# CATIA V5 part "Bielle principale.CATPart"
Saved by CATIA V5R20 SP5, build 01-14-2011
Part number: Bielle principale
Bounding box of the stored display mesh (mm): x -260 to -155, y -330 to 110, z -45 to 85
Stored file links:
  U:\CFAO\Thinkmotion\Bielle principale.CATPart
  U:\CFAO\Thinkmotion\Bras Articule.CATProduct
  U:\CFAO\Thinkmotion\Squelette Bielle principale.CATPart
  U:\CFAO\Thinkmotion\Squelette Corps verin 2.CATPart
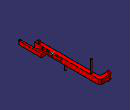
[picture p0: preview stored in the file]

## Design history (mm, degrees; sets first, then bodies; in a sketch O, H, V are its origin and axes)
Set1
  Plane1: linked copy from another document
  Line1: linked copy from another document
  Line2: linked copy from another document
  Point1: linked copy from another document
  Point2: linked copy from another document
  Line3: linked copy from another document
  Point3 to Point5: linked copy from another document
  Plane2: linked copy from another document
  Line4 to Line7: linked copy from another document
  Point6: linked copy from another document
Body1 (main body)
  Sketch1 on Plane1, origin (0, 0, 0), H (1, 0, 0), V (0, 1, 0)
    line L1 (-250, 110) -> (-190, 110)
    line L2 (-190, 110) -> (-190, -270)
    line L3 (-190, -270) -> (-210, -270)
    line L4 (-210, -270) -> (-210, 90)
    line L5 (-210, 90) -> (-250, 90)
    arc A1 centre (-250, 100) radius 10 from (-250, 90) to (-250, 110) cw
    point P7 (-250, 100)
    reference projected line E1 (-200, -100) -> (-200, 50) from Line1
    reference projected line E2 (-200, -100) -> (-200, 50) from Line1
    reference projected line E3 (-200, 100) -> (-250, 100) from Line2
    reference projected point E4 (-250, 100) from Point1
    reference projected point E5 (-200, -250) from Point2
    distance E2 L2 = 10
    radius A1 = 10
    distance L3 E5 = 20
    horizontal: L1 H, L3 H, L5 H
    vertical: L2 V, L4 V
    tangency: A1 L1, A1 L5
    symmetry: L4 L2 E1, L5 L1 E3
    coincidence: P7 E4
  Pad1: profile Sketch1, direction (0, 0, 1), length 14, mirrored extent
  Fillet1: radius 10, on edge [face of Pad1 from Sketch1.L4 | face of Pad1 from Sketch1.L5]
  Fillet2: radius 10, on edge [face of Pad1 from Sketch1.L1 | face of Pad1 from Sketch1.L2]
  Sketch2 on Plane1, origin (0, 0, 0), H (1, 0, 0), V (0, 1, 0)
    circle A1 centre (-200, -250) radius 5
    reference projected point E1 (-200, -250) from Point2
    radius A1 = 5
    concentricity: A1 E1
  Pad2: profile Sketch2, direction (0, 0, 1), length 25, mirrored extent
  Point7: stored without definition
  Point8: stored without definition
  Sketch3 on face of Pad1 from Sketch1.L4, origin (-210, 0, 0), H (0, -1, 0), V (0, 0, 1)
    line L1 (115, -6) -> (195, -6)
    line L2 (195, -6) -> (195, 6)
    line L3 (195, 6) -> (115, 6)
    line L4 (115, 6) -> (115, -6)
    reference projected line E1 (175, 0) -> (35.7285, 0) from Line3
    reference projected line E2 (175, 0) -> (35.7285, 0) from Line3
    reference projected point E3 (175, 0) from Point7
    reference projected point E4 (175, 0) from Point8
    reference projected point E5 (175, 0) from Point3
    distance L1 E2 = 6
    distance L4 L2 = 80
    distance E3 E4 = 0 (reference)
    distance L4 E5 = 60
    horizontal: L1 H, L3 H
    vertical: L2 V, L4 V
    symmetry: L1 L3 E1
  Pocket1: profile Sketch3, direction (1, 0, 0), through (limit type 6)
  Sketch4 on face of Pocket1 from Sketch3.L1, origin (0, 0, -6), H (1, 0, 0), V (0, 1, 0)
    circle A1 centre (-200, -175) radius 5
    reference projected point E1 (-200, -175) from Point3
    radius A1 = 5
    concentricity: A1 E1
  Pad3: profile Sketch4, direction (0, 0, 1), up to the existing solid (limit type 2)
  Sketch5 on start face of Pad1, origin (0, 0, -14), H (1, 0, 0), V (0, -1, 0)
    circle A1 centre (-200, 100) radius 5
    reference projected point E1 (-200, 100) from Point4
    radius A1 = 5
    concentricity: A1 E1
  Pad4: profile Sketch5, direction (0, 0, -1), length 31
  Sketch6 on end face of Pad1, origin (0, 0, 14), H (1, 0, 0), V (0, 1, 0)
    circle A1 centre (-200, 50) radius 5
    reference projected point E1 (-200, 50) from Point5
    radius A1 = 5
    concentricity: A1 E1
  Pad5: profile Sketch6, direction (0, 0, 1), length 71
  Sketch7 on Plane2, origin (0, 0, 0), H (1, 0, 0), V (0, 1, 0)
    circle A1 centre (-250, 100) radius 5
    reference projected point E1 (-250, 100) from Point1
    radius A1 = 5
    concentricity: A1 E1
  Pad6: profile Sketch7, direction (0, 0, 1), length 25, mirrored extent
  Sketch8 on Plane1, origin (0, 0, 0), H (1, 0, 0), V (0, 1, 0)
    line L1 (-190.2467, -195) -> (-155, -195)
    line L2 (-155, -195) -> (-155, -325)
    arc A1 centre (-160, -325) radius 5 from (-155, -325) to (-165, -325) cw
    line L3 (-165, -325) -> (-165, -230)
    line L4 (-165, -230) -> (-190.8841, -230)
    line L5 (-190.8841, -230) -> (-190.8841, -220)
    line L6 (-190.8841, -220) -> (-165, -220)
    point P9 (-165, -220)
    line L7 (-165, -220) -> (-165, -205)
    line L8 (-165, -205) -> (-190.8841, -205)
    point P11 (-190.8841, -205)
    line L9 (-190.8841, -205) -> (-190.8841, -196.0632)
    line L10 (-190.8841, -196.0632) -> (-190.2467, -195)
    circle A2 centre (-160, -325) radius 2.5
    reference projected line E1 (-200, -200) -> (-160, -200) from Line4
    reference projected line E2 (-160, -200) -> (-160, -225) from Line5
    reference projected line E3 (-160, -200) -> (-160, -225) from Line5
    reference projected line E4 (-200, -225) -> (-160, -225) from Line6
    reference projected line E5 (-160, -225) -> (-160, -325) from Line7
    reference projected line E6 (-200, -200) -> (-160, -200) from Line4
    reference projected line E7 (-200, -225) -> (-160, -225) from Line6
    reference projected point E8 (-160, -325) from Point6
    radius A1 = 5
    distance L1 E6 = 5
    distance L6 E7 = 5
    radius A2 = 2.5
    horizontal: L1 H, L4 H, L6 H, L8 H
    vertical: L2 V, L5 V, L7 V, L9 V
    tangency: A1 L2, L3 A1
    coincidence: P9 L3, P11 L5
    symmetry: L1 L8 E1, L7 L2 E2, L6 L4 E4, L3 L2 E5
    parallelism: L7 L2, L2 E3
    concentricity: A1 E8, A2 A1
  Pad7: profile Sketch8, direction (0, 0, 1), length 10, mirrored extent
